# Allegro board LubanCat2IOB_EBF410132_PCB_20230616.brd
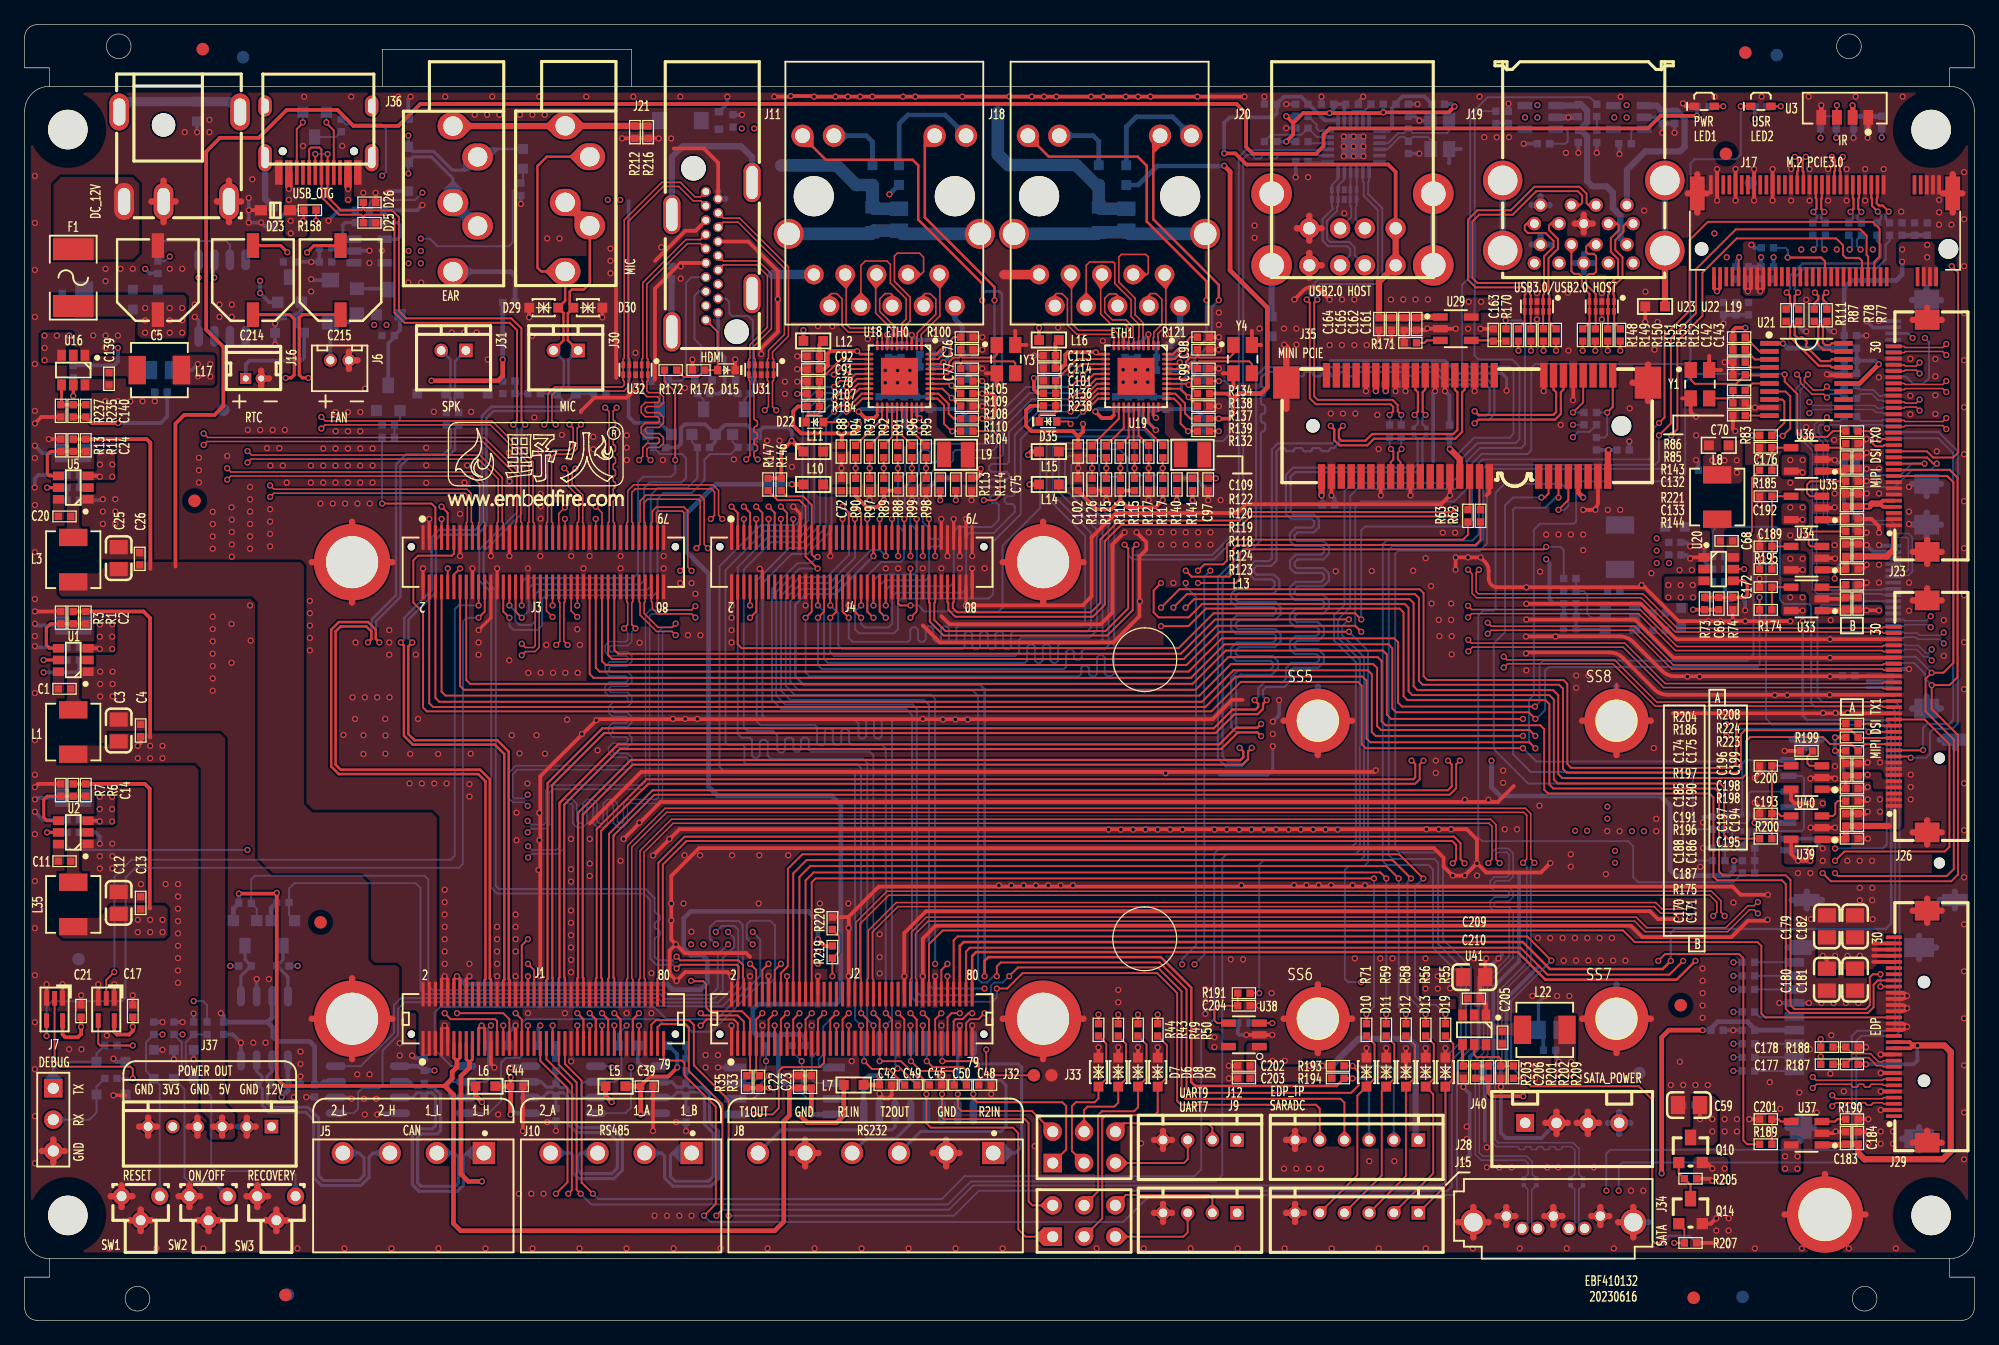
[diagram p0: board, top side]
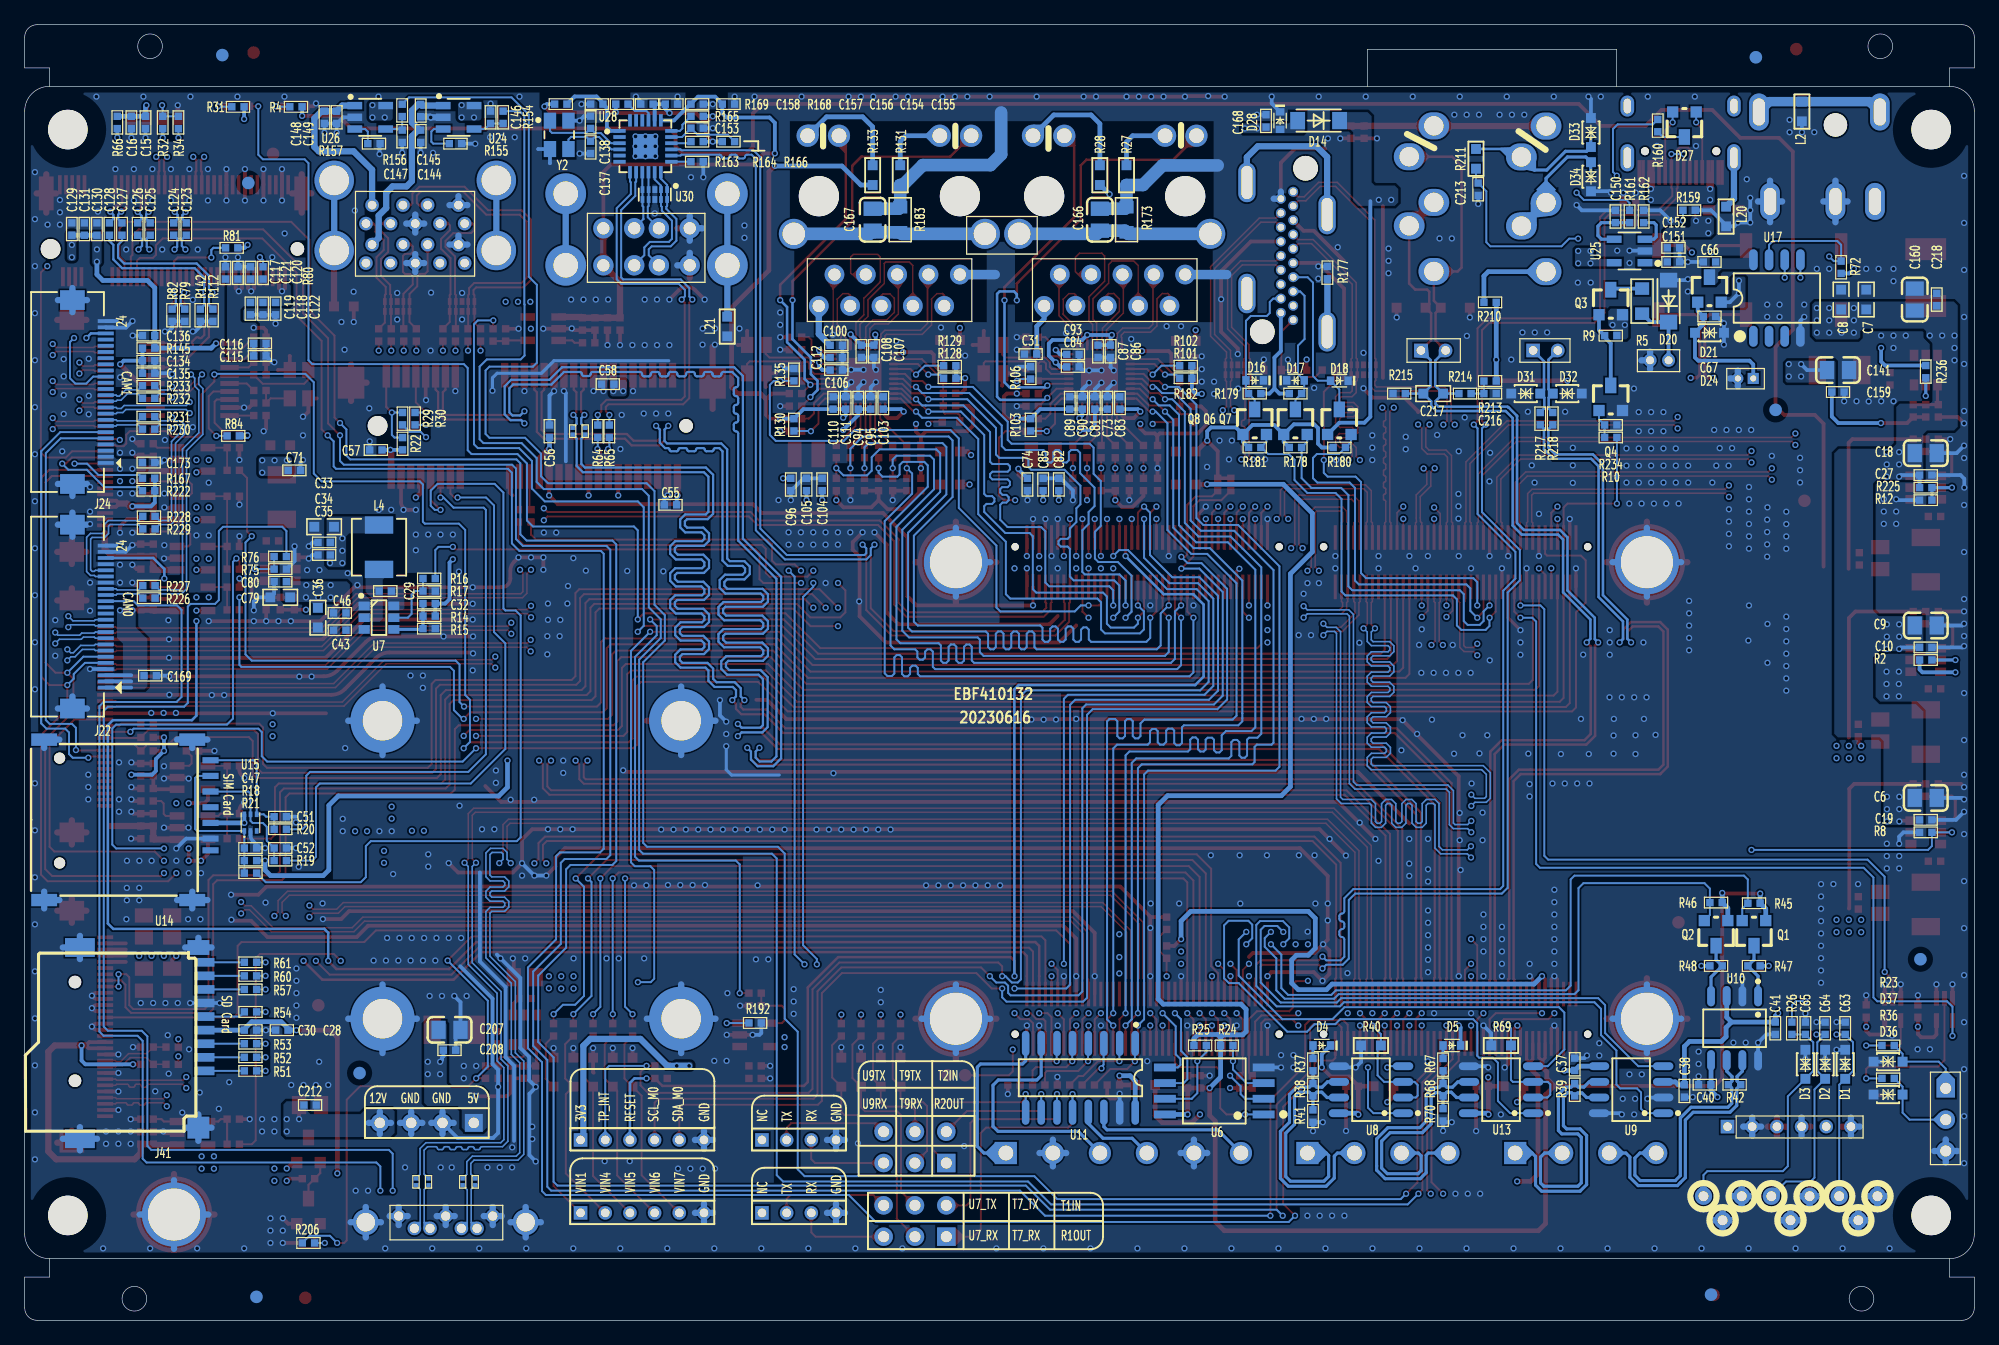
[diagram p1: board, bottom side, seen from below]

Outline 158 x 105 mm; copper layers: TOP, GND02, ART03, ART04, PWR05, BOTTOM. Coordinates in mm from the lower left corner of the outline.
Outline path: circle c7.62,103.25 r1 ; circle c9.14,1.75 r1 ; circle c147.84,103.25 r1 ; circle c149.11,1.75 r1 ; 2,100 arc(0.59,99.41) 0,98 0,7 arc(0.59,5.59) 2,5 ; 2,100 2,101.5 0,101.5 0,104 arc(0.29,104.71) 1,105 157,105 arc(157.71,104.71) 158,104 158,101.5 156,101.5 156,100 ; 2,100 156,100 ; 2,5 2,3.5 0,3.5 0,1 arc(0.29,0.29) 1,0 157,0 arc(157.71,0.29) 158,1 158,3.5 156,3.5 156,5 ; 2,5 156,5 ; 156,5 arc(157.41,5.59) 158,7 158,98 arc(157.41,99.41) 156,100 ; 28.99,100 28.99,103 49.18,103 49.18,100

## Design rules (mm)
net group DIFF_MDI0_PHY0: nets MDIN0_PHY0 MDIP0_PHY0
net group DIFF_MDI0_PHY1: nets MDIN0_PHY1 MDIP0_PHY1
net group DIFF_MDI1_PHY0: nets MDIN1_PHY0 MDIP1_PHY0
net group DIFF_MDI1_PHY1: nets MDIN1_PHY1 MDIP1_PHY1
net group DIFF_MDI2_PHY0: nets MDIN2_PHY0 MDIP2_PHY0
net group DIFF_MDI2_PHY1: nets MDIN2_PHY1 MDIP2_PHY1
net group DIFF_MDI3_PHY0: nets MDIN3_PHY0 MDIP3_PHY0
net group DIFF_MDI3_PHY1: nets MDIN3_PHY1 MDIP3_PHY1
net group DIFF_SATA0RX: nets SATA0RXN SATA0RXP
net group DIFF_SATA0TX: nets SATA0TXN SATA0TXP
net group DIFF_USB2_HOST3_D: nets USB2_HOST3_DM USB2_HOST3_DP
net group DIFF_USB3_HOST1_SSTX: nets USB3_HOST1_SSTXN USB3_HOST1_SSTXP
net group DIFF_USB3_OTG0_D: nets USB3_OTG0_DM USB3_OTG0_DP
net group DIFF_USB30_TX: nets USB30_TXN USB30_TXP
net group DIFF_USB_HUB_D1: nets USB_HUB_DM1 USB_HUB_DP1
net group DIFF_USB_HUB_D2: nets USB_HUB_DM2 USB_HUB_DP2
net group EDP_AUXN: nets EDP_AUXN EDP_TX_AUXN
net group EDP_AUXP: nets EDP_AUXP EDP_TX_AUXP
net group GMAC0_RXCLK: nets GMAC0_RXCLK N15580037
net group GMAC0_RXD0: nets GMAC0_RXD0 N15580021
net group GMAC0_RXD1: nets GMAC0_RXD1 N15580025
net group GMAC0_RXD2: nets GMAC0_RXD2 N15580029
net group GMAC0_RXD3: nets GMAC0_RXD3 N15580033
net group GMAC0_RXDV_CRS: nets GMAC0_RXDV_CRS N15580041
net group GMAC1_RXCLK_M1: nets GMAC1_RXCLK_M1 N15599549
net group GMAC1_RXD0_M1: nets GMAC1_RXD0_M1 N15599533
net group GMAC1_RXD1_M1: nets GMAC1_RXD1_M1 N15599537
net group GMAC1_RXD2_M1: nets GMAC1_RXD2_M1 N15599541
net group GMAC1_RXD3_M1: nets GMAC1_RXD3_M1 N15599545
net group GMAC1_RXDV_CRS_M1: nets GMAC1_RXDV_CRS_M1 N15599553
net group N17639713: nets N17639713 N17697748
net group PCIE20_CLKREQN_M1: nets N17411326 PCIE20_CLKREQN_M1
net group PCIE20_TXN: nets PCIE20_TXN PE_TXN
net group PCIE20_TXP: nets PCIE20_TXP PE_TXP
net group PCIE20_WAKEN_M1: nets N17411312 PCIE20_WAKEN_M1
net group PCIE30_REFCLKN_IN: nets N17639523 PCIE30_REFCLKN_IN
net group PCIE30_REFCLKP_IN: nets N17639486 PCIE30_REFCLKP_IN
net group PCIE30_TX0N: nets PCIE30_TX0N PETN0
net group PCIE30_TX0P: nets PCIE30_TX0P PETP0
net group PCIE30_TX1N: nets PCIE30_TX1N PETN1
net group PCIE30_TX1P: nets PCIE30_TX1P PETP1
net group PWM3_IR: nets N17536407 PWM3_IR
net group SDMMC0_CLK: nets N17407474 SDMMC0_CLK
net group SDMMC0_CMD: nets N17407476 SDMMC0_CMD
net group SDMMC0_D0: nets N17407472 SDMMC0_D0
net group SDMMC0_D1: nets N17407480 SDMMC0_D1
net group SDMMC0_D2: nets N17407470 SDMMC0_D2
net group SDMMC0_D3: nets N17407478 SDMMC0_D3
net group USB20_DM1: nets USB2_HOST2_DM USB20_DM1
net group USB20_DP1: nets USB2_HOST2_DP USB20_DP1
net group USB30_DM: nets USB3_HOST1_DM USB30_DM
net group USB30_DP: nets USB3_HOST1_DP USB30_DP
net group USB30_RXN: nets USB3_HOST1_SSRXN USB30_RXN
net group USB30_RXP: nets USB3_HOST1_SSRXP USB30_RXP
net group USB_HUB_DM3: nets N17411507 USB_HUB_DM3
net group USB_HUB_DP3: nets N17411481 USB_HUB_DP3
net group ADC: nets SARADC_VIN1 SARADC_VIN4 SARADC_VIN5 SARADC_VIN6 SARADC_VIN7
net group FSPI: nets FSPI_CLK FSPI_CS0N FSPI_D0 FSPI_D1 FSPI_D2 FSPI_D3
net group MIPI_CSI_RX_D2N: nets MIPI_CSI_RX_D2N N17546373 N17737043
net group MIPI_CSI_RX_D2P: nets MIPI_CSI_RX_D2P N17546411 N17737040
net group MIPI_CSI_RX_D3N: nets MIPI_CSI_RX_D3N N17546367 N17737138
net group MIPI_CSI_RX_D3P: nets MIPI_CSI_RX_D3P N17546399 N17737126
net group PWR: nets 1V05_AVDD_PHY0 1V05_AVDD_PHY1 1V05_DVDD_PHY0 1V05_DVDD_PHY1 3V3_AVDD_PHY0 3V3_AVDD_PHY1 HUB_3V3 RS232_3V3 RS485_1_3V3 RS485_2_3V3 SIM_VDD VCC3V3_SD VCC5V0_USB20_HOST2 VCC5V0_USB20_HUB VCC5V0_USB30_HOST VCC_1V8 VCCA_1V8 VCCIO_ACODEC VDD_3V3_EDP_LCD VDD_LCD0_3V3
net group REFCLKN: nets N17639617 REF_CLKN REFCLKN
net group REFCLKP: nets N17639615 REF_CLKP REFCLKP

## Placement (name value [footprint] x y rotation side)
C1  0.1uF  [C0402]  3.23 51.18 0 top
C2  NC  [C0402]  4.95 56.94 90 top
C3  22uF  [C0805]  7.62 47.8 90 top
C4  0.1uF  [C0402]  9.4 47.8 90 top
C5  100uF  [EC6P3]  10.79 84.3 180 top
C6  22uF  [C0805]  3.94 42.34 180 bottom
C7  4.7uF  [C0603]  8.76 82.72 90 bottom
C8  0.1uF  [C0603]  10.79 82.72 90 bottom
C9  22uF  [C0805]  3.94 56.31 180 bottom
C10  0.1uF  [C0402]  3.94 54.53 180 bottom
C11  0.1uF  [C0402]  3.23 37.21 0 top
C12  22uF  [C0805]  7.62 33.83 90 top
C13  0.1uF  [C0402]  9.4 33.83 90 top
C14  NC  [C0402]  4.95 42.97 90 top
C15  0.1uF  [C0402]  148.21 97.07 270 bottom
C16  4.7uF  [C0402]  149.35 97.07 270 bottom
C17  0.1uF  [C0402]  8.76 25.07 90 top
C18  22uF  [C0805]  3.94 70.28 180 bottom
C19  0.1uF  [C0402]  3.94 40.56 180 bottom
C20  0.1uF  [C0402]  3.23 65.15 0 top
C21  0.1uF  [C0402]  4.57 25.07 90 top
C22  10uF  [C0402]  62.74 19.33 90 top
C23  0.1uF  [C0402]  63.75 19.33 90 top
C24  NC  [C0402]  4.95 70.91 90 top
C25  22uF  [C0805]  7.62 61.77 90 top
C26  0.1uF  [C0402]  9.32 61.71 90 top
C27  0.1uF  [C0402]  3.94 68.5 180 bottom
C28  10uF  [C0402]  137.16 23.52 0 bottom
C29  0.1uF  [C0402]  128.78 59.1 180 bottom
C30  0.1uF  [C0402]  139.7 23.52 180 bottom
C31  0.1uF  [C0402]  76.48 78.3 0 bottom
C32  NC  [C0402]  125.22 58.09 0 bottom
C33  22uF  [C0603]  133.73 64.31 0 bottom
C34  1uF  [C0402]  133.73 63.04 0 bottom
C35  0.1uF  [C0402]  133.73 62.02 0 bottom
C36  22uF  [C0603]  134.24 56.94 270 bottom
C37  0.1uF  [C0402]  32.38 20.75 90 bottom
C38  0.1uF  [C0402]  23.5 18.59 270 bottom
C39  0.1uF  [C0402]  50.42 18.97 0 top
C40  0.1uF  [C0402]  21.84 19.1 0 bottom
C41  0.1uF  [C0402]  16.13 23.67 270 bottom
C42  0.1uF  [C0402]  69.77 19.07 0 top
C43  10uF  [C0402]  132.46 55.93 0 bottom
C44  0.1uF  [C0402]  39.88 18.97 0 top
C45  0.1uF  [C0402]  73.81 19.07 0 top
C46  0.1uF  [C0402]  132.46 57.32 0 bottom
C47  33pF  [C0402]  139.7 38.27 180 bottom
C48  0.1uF  [C0402]  77.83 19.07 0 top
C49  0.1uF  [C0402]  71.81 19.07 180 top
C50  0.1uF  [C0402]  75.82 19.07 180 top
C51  33pF  [C0402]  137.29 40.81 180 bottom
C52  33pF  [C0402]  137.29 38.27 180 bottom
C53  0.1uF  [C0201]  113.59 72.06 90 bottom
C54  0.1uF  [C0201]  112.57 72.06 90 bottom
C55  0.1uF  [C0402]  105.66 66.09 0 bottom
C56  0.1uF  [C0402]  115.47 72.06 90 bottom
C57  0.1uF  [C0402]  129.54 70.53 0 bottom
C58  0.1uF  [C0402]  110.74 75.87 0 bottom
C59  22uF  [C0805]  134.87 17.45 180 top
C60  10nF  [C0201]  121.49 11.22 270 bottom
C61  10nF  [C0201]  122.5 11.22 270 bottom
C62  10nF  [C0201]  125.27 11.22 270 bottom
C63  0.1uF  [C0402]  10.46 23.67 90 bottom
C64  0.1uF  [C0402]  12.09 23.67 90 bottom
C65  0.1uF  [C0402]  13.69 23.67 90 bottom
C66  0.1uF  [C0402]  21.46 85.77 0 bottom
C67  10uF  [C0402]  21.46 81.35 180 bottom
C68  0.1uF  [C0402]  137.92 63.17 180 top
C69  NC  [C0402]  137.29 58.09 270 top
C70  22uF  [C0603]  137.29 70.91 180 top
C71  0.1uF  [C0402]  136.14 68.88 180 bottom
C72  0.1uF  [C0402]  66.19 67.74 90 top
C73  0.1uF  [C0402]  70.26 74.34 90 bottom
C74  0.1uF  [C0402]  76.73 67.74 270 bottom
C75  4.7uF  [C0402]  76.73 67.74 270 top
C76  18pF  [C0402]  76.35 78.66 0 top
C77  18pF  [C0402]  76.35 77.14 0 top
C78  0.1uF  [C0402]  63.91 76.07 180 top
C79  22uF  [C0603]  137.29 58.59 0 bottom
C80  0.1uF  [C0402]  137.29 59.86 0 bottom
C81  0.1uF  [C0402]  71.27 74.34 90 bottom
C82  0.1uF  [C0402]  74.19 67.74 90 bottom
C83  0.1uF  [C0402]  69.24 74.34 90 bottom
C84  0.1uF  [C0402]  73.05 77.26 180 bottom
C85  0.1uF  [C0402]  75.46 67.74 90 bottom
C86  0.1uF  [C0402]  70 78.53 270 bottom
C87  0.1uF  [C0402]  71.02 78.53 270 bottom
C88  0.1uF  [C0402]  66.19 70.4 270 top
C89  0.1uF  [C0402]  73.3 74.34 90 bottom
C90  0.1uF  [C0402]  72.29 74.34 90 bottom
C91  0.1uF  [C0402]  63.91 77.09 180 top
C92  0.1uF  [C0402]  63.91 78.13 180 top
C93  0.1uF  [C0402]  73.05 78.28 180 bottom
C94  0.1uF  [C0402]  90.45 74.34 90 bottom
C95  0.1uF  [C0402]  89.43 74.34 90 bottom
C96  0.1uF  [C0402]  95.91 67.74 270 bottom
C97  4.7uF  [C0402]  95.91 67.74 270 top
C98  18pF  [C0402]  95.53 78.66 0 top
C99  18pF  [C0402]  95.53 77.14 0 top
C100  0.1uF  [C0402]  92.23 79.02 180 bottom
C101  0.1uF  [C0402]  83.06 76.15 180 top
C102  0.1uF  [C0402]  85.37 67.74 90 top
C103  0.1uF  [C0402]  88.42 74.34 90 bottom
C104  0.1uF  [C0402]  93.37 67.74 90 bottom
C105  0.1uF  [C0402]  94.64 67.74 90 bottom
C106  0.1uF  [C0402]  92.23 77.01 180 bottom
C107  0.1uF  [C0402]  89.18 78.53 270 bottom
C108  0.1uF  [C0402]  90.2 78.53 270 bottom
C109  0.1uF  [C0402]  85.37 70.4 270 top
C110  0.1uF  [C0402]  92.48 74.34 90 bottom
C111  0.1uF  [C0402]  91.47 74.34 90 bottom
C112  0.1uF  [C0402]  92.23 78.02 180 bottom
C113  0.1uF  [C0402]  83.03 78.18 180 top
C114  0.1uF  [C0402]  83.03 77.16 180 top
C115  1uF  [C0402]  138.94 78.15 180 bottom
C116  0.1uF  [C0402]  138.94 79.17 180 bottom
C117  0.1uF  [C0402]  141.73 84.88 90 bottom
C118  0.1uF  [C0402]  138.68 81.99 270 bottom
C119  0.1uF  [C0402]  139.7 81.99 270 bottom
C120  0.1uF  [C0402]  139.7 84.88 90 bottom
C121  0.1uF  [C0402]  140.72 84.88 90 bottom
C122  0.1uF  [C0402]  137.67 81.99 270 bottom
C123  0.22uF  [C0402]  144.91 88.44 90 bottom
C124  0.22uF  [C0402]  145.92 88.44 90 bottom
C125  0.22uF  [C0402]  147.83 88.44 90 bottom
C126  0.22uF  [C0402]  148.84 88.44 90 bottom
C127  0.22uF  [C0402]  150.11 88.44 90 bottom
C128  0.22uF  [C0402]  151.13 88.44 90 bottom
C129  0.1uF  [C0402]  154.18 88.44 90 bottom
C130  0.1uF  [C0402]  152.15 88.44 90 bottom
C131  0.1uF  [C0402]  153.16 88.44 90 bottom
C132  18pF  [C0402]  138.94 76.63 180 top
C133  18pF  [C0402]  138.94 74.34 0 top
C134  0.1uF  [C0402]  147.96 77.77 180 bottom
C135  1uF  [C0402]  147.96 76.75 180 bottom
C136  4.7uF  [C0402]  147.96 79.8 0 bottom
C137  NC  [C0402]  112.14 95.05 270 bottom
C138  NC  [C0402]  112.14 97.09 90 bottom
C139  0.1uF  [C0402]  6.83 76.3 90 top
C140  NC  [C0402]  4.95 73.71 270 top
C141  22uF  [C0805]  11.05 77.01 180 bottom
C142  0.1uF  [C0402]  128.3 79.85 270 top
C143  0.1uF  [C0402]  129.31 79.85 270 top
C144  10uF  [C0402]  125.91 95.96 270 bottom
C145  0.1uF  [C0402]  125.91 98.04 270 bottom
C146  0.1uF  [C0402]  120.24 97.49 90 bottom
C147  0.1uF  [C0402]  127.41 95.96 270 bottom
C148  10uF  [C0402]  133.71 97.49 270 bottom
C149  0.1uF  [C0402]  132.72 97.49 270 bottom
C150  0.1uF  [C0402]  29.08 89.45 90 bottom
C151  10uF  [C0402]  24.38 85.77 180 bottom
C152  0.1uF  [C0402]  24.38 86.91 180 bottom
C153  0.1uF  [C0402]  103.5 96.62 180 bottom
C154  10uF  [C0402]  103.5 98.56 180 bottom
C155  0.1uF  [C0402]  100.97 98.56 180 bottom
C156  0.1uF  [C0402]  105.59 98.56 180 bottom
C157  10uF  [C0402]  107.57 98.56 0 bottom
C158  10nF  [C0402]  111.63 98.56 0 bottom
C159  0.1uF  [C0402]  11.05 75.23 180 bottom
C160  22uF  [C0805]  4.83 82.72 90 bottom
C161  10uF  [C0402]  112.8 80.74 270 top
C162  0.1uF  [C0402]  111.79 80.74 270 top
C163  0.1uF  [C0402]  119.02 79.85 90 top
C164  1uF  [C0402]  109.75 80.74 270 top
C165  1uF  [C0402]  110.77 80.74 270 top
C166  1nF  [C0805]  70.87 89.19 90 bottom
C167  1nF  [C0805]  89.28 89.19 90 bottom
C168  1uF  [C0402]  57.4 97.2 90 bottom
C169  10uF  [C0402]  147.83 52.24 180 bottom
C170  10uF  [C0402]  147.57 58.09 90 top
C171  0.1uF  [C0402]  148.59 58.09 90 top
C172  0.1uF  [C0402]  141.1 59.42 180 top
C173  10uF  [C0402]  147.96 69.52 180 bottom
C174  10uF  [C0402]  147.57 69.52 90 top
C175  0.1uF  [C0402]  148.59 69.52 90 top
C176  0.1uF  [C0402]  141.1 70.72 180 top
C177  0.1uF  [C0402]  146.05 20.75 0 top
C178  0.1uF  [C0402]  146.05 22.14 0 top
C179  10uF  [C0805]  146.05 31.92 90 top
C180  10uF  [C0805]  146.05 27.61 270 top
C181  10uF  [C0805]  148.34 27.61 270 top
C182  10uF  [C0805]  148.34 31.92 90 top
C183  10uF  [C0402]  147.57 14.78 90 top
C184  0.1uF  [C0402]  148.59 14.78 90 top
C185  0.1uF  [C0402]  147.57 66.47 90 top
C186  10uF  [C0402]  148.59 62.4 90 top
C187  10uF  [C0402]  148.08 60.88 0 top
C188  0.1uF  [C0402]  147.57 62.4 90 top
C189  0.1uF  [C0402]  141.1 62.72 180 top
C190  10uF  [C0402]  148.59 66.47 90 top
C191  0.1uF  [C0402]  148.08 64.94 0 top
C192  0.1uF  [C0402]  141.1 66.78 180 top
C193  0.1uF  [C0402]  141.1 41.07 180 top
C194  10uF  [C0402]  148.59 40.56 90 top
C195  0.1uF  [C0402]  148.08 39.04 0 top
C196  0.1uF  [C0402]  147.57 44.62 90 top
C197  10uF  [C0402]  147.57 40.56 90 top
C198  0.1uF  [C0402]  148.08 43.1 0 top
C199  10uF  [C0402]  148.59 44.62 90 top
C200  0.1uF  [C0402]  141.1 44.94 180 top
C201  0.1uF  [C0402]  141.1 16.3 180 top
C202  10uF  [C0402]  98.81 20.62 180 top
C203  0.1uF  [C0402]  98.81 19.6 180 top
C204  0.1uF  [C0402]  98.81 25.5 0 top
C205  0.1uF  [C0402]  119.76 22.91 90 top
C206  NC  [C0402]  117.6 20.11 270 top
C207  22uF  [C0805]  123.57 23.54 180 bottom
C208  0.1uF  [C0402]  123.57 21.89 180 bottom
C209  22uF  [C0805]  117.47 27.81 0 top
C210  0.1uF  [C0402]  117.45 26.08 0 top
C211  10nF  [C0201]  126.29 11.22 270 bottom
C212  0.1uF  [C0402]  134.87 17.45 180 bottom
C213  1uF  [C0402]  40.21 91.66 270 bottom
C214  220uF  [EC6P3]  18.5 84.3 180 top
C215  220uF  [EC6P3]  25.6 84.3 180 top
C216  1uF  [C0402]  39.24 75.1 180 bottom
C217  100pF  [C0603]  43.85 75.1 0 bottom
C218  0.1uF  [C0402]  3.05 82.72 90 bottom
D1  PESD3V3L1BA  [SOD323_T]  10.46 20.75 270 bottom
D2  PESD3V3L1BA  [SOD323_T]  12.09 20.75 270 bottom
D3  PESD3V3L1BA  [SOD323_T]  13.69 20.75 270 bottom
D4  RB521S-30  [SOD523]  52.88 22.27 0 bottom
D5  RB521S-30  [SOD523]  42.34 22.27 0 bottom
D6  PESD3V3L1BA  [SOD323_T]  88.62 20.11 90 top
D7  PESD3V3L1BA  [SOD323_T]  87.02 20.11 90 top
D8  PESD3V3L1BA  [SOD323_T]  90.22 20.11 90 top
D9  PESD3V3L1BA  [SOD323_T]  91.82 20.11 90 top
D10  PESD3V3L1BA  [SOD323_T]  108.74 20.11 90 top
D11  PESD3V3L1BA  [SOD323_T]  110.34 20.11 90 top
D12  PESD3V3L1BA  [SOD323_T]  111.94 20.11 90 top
D13  PESD3V3L1BA  [SOD323_T]  113.54 20.11 90 top
D14  1N5819W  [SOD-123]  53.14 97.23 180 bottom
D15  ESD5B5.0ST1G  [SOD523]  56.87 77.01 180 top
D16  ESD5B5.0ST1G  [SOD523]  58.32 76.17 0 bottom
D17  ESD5B5.0ST1G  [SOD523]  55.02 76.17 180 bottom
D18  ESD5B5.0ST1G  [SOD523]  51.46 76.15 0 bottom
D19  PESD3V3L1BA  [SOD323_T]  115.14 20.11 90 top
D20  1N4148W  [SOD-123]  24.78 82.6 270 bottom
D21  BAT54C  [SOT23]  21.46 83.5 180 bottom
D22  RB521S-30  [SOD523]  64.03 72.79 0 top
D23  PESD5V0S1BA-N  [SOD323]  20.32 89.96 0 top
D24  PESD3V3L1BA  [SOD323_T]  21.46 80.03 0 bottom
D25  KLXES15AAA1  [ES0402]  27.94 88.95 0 top
D26  KLXES15AAA1  [ES0402]  27.94 90.6 0 top
D27  BAT54A  [SOT23]  23.5 96.94 0 bottom
D28  ESD5B5.0ST1G  [SOD523]  56.26 97.23 270 bottom
D29  PESD3V3L1BA  [SOD323_T]  42.06 82.06 180 top
D30  PESD3V3L1BA  [SOD323_T]  45.64 82.06 0 top
D31  PESD3V3L1BA  [SOD323_T]  36.35 75.1 0 bottom
D32  PESD3V3L1BA  [SOD323_T]  32.99 75.1 180 bottom
D33  PESD3V3L1BA  [SOD323_T]  31.07 96.26 90 bottom
D34  PESD3V3L1BA  [SOD323_T]  31.06 92.68 270 bottom
D35  RB521S-30  [SOD523]  82.93 72.84 0 top
D36  PESD3V3L1BA  [SOD323_T]  6.99 18.29 0 bottom
D37  PESD3V3L1BA  [SOD323_T]  6.99 20.96 0 bottom
F1  SMD1812P200TF16  [F1812]  3.94 84.5 270 top
J1  -  [SGDBM-05-80P-H10]  42.03 24.44 0 top
J2  -  [SGDBM-05-80P-H10]  67.03 24.44 0 top
J3  -  [SGDBF-05-80P-H30]  42.03 61.44 180 top
J4  -  [SGDBF-05-80P-H30]  67.03 61.44 180 top
J5  CON4  [DB2ERC-3P81-4P]  31.5 13.56 180 top
J6  A1501WV-2P  [ZH1P5MM_TH_2P]  25.53 77.8 0 top
J7  1X3PIN-M  [DIP_3P_2P54]  2.32 16.26 270 top
J8  CON6  [DB2ERC-3P81-6P]  68.96 13.56 180 top
J9  PH-4A  [PH-1X4-2P0]  95.25 8.71 180 top
J10  CON4  [DB2ERC-3P81-4P]  48.33 13.56 180 top
J11  -  [HY911130A]  69.66 91.1 0 top
J12  PH-4A  [PH-1X4-2P0]  95.25 14.62 180 top
J13  2X3PIN-M  [DIP-2X3-2P54]  85.85 8.05 0 top
J14  2X3PIN-M  [DIP-2X3-2P54]  85.85 14.02 0 top
J15  PH-6A  [PH-1X6-2P0]  107.95 8.71 180 top
J16  1.25T-2A  [GH1P25_TH_2P]  18.54 76.33 0 top
J17  -  [M2_NGFF_M_KEY]  145.9 88.3 0 top
J18  -  [HY911130A]  87.92 91.1 0 top
J19  USB3D0_USB2D0-A-D  [USB3D0-AF-18P]  126.35 88.88 180 top
J20  -  [USB-A-D]  107.6 92 0 top
J21  HDMI-001C  [HDMI-SMD]  55.7 86.16 90 top
J22  FPC_0P5_24P_D  [FPC_24P_0P5]  152.78 57.03 90 bottom
J23  FPC_0R5_30P_D  [FPC-30P-0P5]  152.83 71.67 90 top
J24  FPC_0P5_24P_D  [FPC_24P_0P5]  152.78 75.23 90 bottom
J25  PJ-325C5-G  [EAR_JACK]  34.71 90.58 270 top
J26  FPC_0R5_30P_D  [FPC-30P-0P5]  152.83 48.94 90 top
J27  PJ-325C5-R  [EAR_JACK]  43.8 90.6 270 top
J28  PH-6A  [PH-1X6-2P0]  107.95 14.62 180 top
J29  FPC_0R5_30P_D  [FPC-30P-0P5]  152.83 23.8 90 top
J30  PH  [PH-1X2-2P0_L]  43.85 78.6 180 top
J31  PH  [PH-1X2-2P0_L]  34.76 78.6 180 top
J32  TP  [TP_1MM]  81.79 19.86 180 top
J33  TP  [TP_1MM]  83.21 19.86 180 top
J34  SATA  [SSATA_V]  123.88 8.45 0 top
J35  MINI-PCIE  [PCIE_52P]  116.9 72.49 180 top
J36  TYPE-C  [TYPE-C-31-M-12]  23.8 93.31 180 top
J37  PH-6A  [PH-1X6-2P0]  15 15.7 180 top
J39  DC-044A-20A  [DC_IN_TH_3P_10R1X11R6]  12.55 94.3 270 top
J40  CON4  [XH2P54-4P]  125.41 16 0 top
J41  TF_Card  [TFCARD]  153.92 23.41 270 bottom
L1  3.3uH  [L4520]  3.93 47.67 270 top
L2  100R 100MHz  [L0603]  13.97 97.96 270 bottom
L3  3.3uH  [L4520]  3.93 61.64 270 top
L4  3.3uH  [L4520]  129.28 62.66 90 bottom
L5  100R 100MHz  [L0603]  47.88 18.97 0 top
L6  100R 100MHz  [L0603]  37.34 18.97 0 top
L7  100R 100MHz  [L0603]  67.18 19.07 180 top
L8  3.3uH  [L4520]  137.16 66.72 90 top
L9  2.2uH  [L2520]  75.46 70.15 0 top
L10  100R 100MHz  [L0603]  63.91 67.74 180 top
L11  100R 100MHz  [L0603]  63.91 70.4 180 top
L12  100R 100MHz  [L0603]  63.91 79.37 180 top
L13  2.2uH  [L2520]  94.64 70.15 0 top
L14  100R 100MHz  [L0603]  83.01 67.74 180 top
L15  100R 100MHz  [L0603]  83.01 70.4 180 top
L16  100R 100MHz  [L0603]  83.01 79.45 180 top
L17  3.3uH  [L4520]  10.92 77.01 0 top
L19  100R 100MHz  [L0603]  132.13 82.17 180 top
L20  100R 100MHz  [L0603]  20.12 89.45 270 bottom
L21  100R 100MHz  [L0603]  101.07 80.54 270 bottom
L22  3.3uH  [L4520]  123.19 23.54 0 top
L35  3.3uH  [L4520]  3.93 33.7 270 top
LED1  HS-0602-UR  [LED_HS_0602_UR]  136.1 98.39 0 top
LED2  HS-0602-UG  [LED_HS_0602_UR]  140.7 98.39 0 top
NOREF  -  [unnamed]  13.77 66.42 0 top
NOREF#2  -  [unnamed]  21.13 2.05 0 top
NOREF#3  -  [unnamed]  137.87 94.53 0 top
NOREF#4  -  [#2]  0 7.1 0 top
NOREF#5  -  [unnamed]  139.45 102.74 0 top
NOREF#6  -  [unnamed]  134.2 25.53 0 top
NOREF#7  -  [unnamed]  23.98 32.25 0 top
NOREF#8  -  [unnamed]  135.25 1.82 0 top
NOREF#9  -  [#2]  2 5 90 top
NOREF#10  -  [unnamed]  14.43 103.02 0 top
NOREF#11  -  [unnamed]  139.88 92.17 180 bottom
NOREF#12  -  [unnamed]  16.1 73.78 180 bottom
NOREF#13  -  [unnamed]  141.99 102.54 180 bottom
NOREF#14  -  [unnamed]  139.22 1.9 180 bottom
NOREF#15  -  [unnamed]  17.7 102.36 180 bottom
NOREF#16  -  [unnamed]  21.34 2.08 180 bottom
NOREF#17  -  [unnamed]  4.37 29.26 180 bottom
NOREF#18  -  [unnamed]  130.86 20.04 180 bottom
Q1  2SK3018  [SOT23]  17.86 31.4 0 bottom
Q2  2SK3018  [SOT23]  20.93 31.4 0 bottom
Q3  SSM3J328R-LF  [SOT23]  29.46 82.48 180 bottom
Q4  SS8050  [SOT23]  29.46 74.72 180 bottom
Q6  2SK3018  [SOT23]  55.02 72.78 180 bottom
Q7  2SK3018  [SOT23]  51.46 72.78 180 bottom
Q8  2SK3018  [SOT23]  58.32 72.78 180 bottom
Q10  SSM3J328R-LF  [SOT23]  135 13.78 0 top
Q14  2SK3018  [SOT23]  135 8.82 0 top
R1  115K  [R0402]  3.94 56.94 90 top
R2  1K  [R0402]  3.94 53.51 0 bottom
R3  20K  [R0402]  2.92 56.94 90 top
R4  5.1K  [R0402]  136.02 98.34 0 bottom
R5  10R  [R0805]  26.92 82.6 270 bottom
R6  100K  [R0402]  3.94 42.97 90 top
R7  30K  [R0402]  2.92 42.97 90 top
R8  1K  [R0402]  3.94 39.54 0 bottom
R9  10K  [R0402]  29.46 79.8 0 bottom
R10  1K  [R0402]  29.46 71.55 0 bottom
R11  115K  [R0402]  3.94 70.91 90 top
R12  27K  [R0402]  3.94 66.47 0 bottom
R13  20K  [R0402]  2.92 70.91 90 top
R14  100K  [R0402]  125.22 57.07 0 bottom
R15  30K  [R0402]  125.22 56.05 180 bottom
R16  1K  [R0402]  125.22 60.12 0 bottom
R17  10K  [R0402]  125.22 59.1 180 bottom
R18  15K  [R0402]  139.7 37.26 0 bottom
R19  0R  [R0402]  137.29 37.26 0 bottom
R20  0R  [R0402]  137.29 39.8 0 bottom
R21  0R  [R0402]  139.7 36.24 0 bottom
R22  4.7K  [R0402]  127.38 71.04 90 bottom
R23  100R  [R0402]  6.99 22.27 0 bottom
R24  10K  [R0402]  60.58 22.27 180 bottom
R25  10K  [R0402]  62.74 22.27 180 bottom
R26  100R  [R0402]  14.78 23.67 90 bottom
R27  510R  [R0603]  68.71 92.81 270 bottom
R28  510R  [R0603]  70.87 92.81 270 bottom
R29  22R  [R0402]  127.38 73.07 90 bottom
R30  22R  [R0402]  126.36 73.07 90 bottom
R31  4.7K  [R0402]  140.72 98.34 0 bottom
R32  10K  [R0402]  146.81 97.07 90 bottom
R33  2.2K  [R0402]  59.54 19.33 90 top
R34  22R  [R0402]  145.54 97.07 90 bottom
R35  2.2K  [R0402]  58.52 19.33 90 top
R36  100R  [R0402]  6.99 19.6 0 bottom
R37  4.7K  [R0402]  53.59 20.72 90 bottom
R38  120R  [R0402]  53.59 18.69 90 bottom
R39  120R  [R0402]  32.38 18.69 90 bottom
R40  10K  [R0603]  48.9 22.27 0 bottom
R41  4.7K  [R0402]  53.59 16.56 270 bottom
R42  120R  [R0402]  19.43 19.1 0 bottom
R43  100R  [R0402]  88.62 23.54 270 top
R44  100R  [R0402]  87.02 23.54 270 top
R45  10K  [R0402]  17.86 33.8 0 bottom
R46  10K  [R0402]  20.93 33.85 0 bottom
R47  10K  [R0402]  17.86 28.72 0 bottom
R48  10K  [R0402]  20.93 28.72 180 bottom
R49  100R  [R0402]  90.22 23.54 270 top
R50  100R  [R0402]  91.82 23.54 270 top
R51  22R  [R0402]  139.7 20.22 0 bottom
R52  22R  [R0402]  139.7 21.32 0 bottom
R53  22R  [R0402]  139.7 22.41 0 bottom
R54  22R  [R0402]  139.7 25 0 bottom
R55  100R  [R0402]  115.14 23.54 270 top
R56  100R  [R0402]  113.54 23.54 270 top
R57  22R  [R0402]  139.7 26.81 0 bottom
R58  100R  [R0402]  111.94 23.54 270 top
R59  100R  [R0402]  110.34 23.54 270 top
R60  22R  [R0402]  139.7 27.92 0 bottom
R61  0R  [R0402]  139.7 29.02 0 bottom
R62  1K  [R0402]  117.98 65.2 270 top
R63  1K  [R0402]  116.97 65.2 270 top
R64  2.2R  [R0402]  111.56 72.06 90 bottom
R65  2.2R  [R0402]  110.62 72.06 90 bottom
R66  22R  [R0402]  150.5 97.07 270 bottom
R67  4.7K  [R0402]  43.05 20.72 90 bottom
R68  120R  [R0402]  43.05 18.69 90 bottom
R69  10K  [R0603]  38.35 22.27 0 bottom
R70  4.7K  [R0402]  43.05 16.66 270 bottom
R71  100R  [R0402]  108.74 23.54 270 top
R72  4.7K  [R0402]  10.79 85.34 90 bottom
R73  100K  [R0402]  136.14 58.09 270 top
R74  30K  [R0402]  138.43 58.09 270 top
R75  10K  [R0402]  137.29 60.88 180 bottom
R76  1K  [R0402]  137.29 61.9 180 bottom
R77  33R  [R0402]  146.05 81.45 90 top
R78  33R  [R0402]  145.03 81.45 90 top
R79  49.9R  [R0402]  145.03 81.45 270 bottom
R80  10K  [R0402]  138.68 84.88 270 bottom
R81  10K  [R0402]  141.22 86.91 180 bottom
R82  49.9R  [R0402]  146.05 81.45 270 bottom
R83  10K  [R0402]  141.1 71.73 0 top
R84  4.7K  [R0402]  141.1 71.67 0 bottom
R85  10K  [R0402]  138.94 78.66 0 top
R86  10K  [R0402]  138.94 79.68 0 top
R87  33R  [R0402]  143.76 81.45 90 top
R88  4.7K  [R0402]  70.76 67.74 90 top
R89  4.7K  [R0402]  69.62 67.74 90 top
R90  4.7K  [R0402]  67.34 67.74 90 top
R91  22R  [R0402]  70.76 70.4 90 top
R92  22R  [R0402]  69.62 70.4 90 top
R93  22R  [R0402]  68.48 70.4 90 top
R94  22R  [R0402]  67.34 70.4 90 top
R95  22R  [R0402]  73.05 70.4 90 top
R96  22R  [R0402]  71.91 70.4 90 top
R97  4.7K  [R0402]  68.48 67.74 270 top
R98  4.7K  [R0402]  73.05 67.74 270 top
R99  4.7K  [R0402]  71.91 67.74 270 top
R100  2.49K  [R0402]  76.35 79.68 0 top
R101  4.7K  [R0402]  63.91 76.35 0 bottom
R102  4.7K  [R0402]  63.91 77.36 0 bottom
R103  4.7K  [R0402]  76.48 72.57 270 bottom
R104  NC  [R0402]  76.35 72.06 180 top
R105  100R  [R0402]  76.35 76.12 180 top
R106  120R  [R0402]  76.48 76.78 90 bottom
R107  10K  [R0402]  63.91 75.08 0 top
R108  4.7K  [R0402]  76.35 74.09 0 top
R109  4.7K  [R0402]  76.35 75.1 0 top
R110  4.7K  [R0402]  76.35 73.07 0 top
R111  33R  [R0402]  142.75 81.45 90 top
R112  49.9R  [R0402]  142.75 81.45 270 bottom
R113  0R  [R0402]  74.19 67.74 90 top
R114  0R  [R0402]  75.46 67.74 270 top
R115  4.7K  [R0402]  89.94 67.74 90 top
R116  4.7K  [R0402]  88.8 67.74 90 top
R117  4.7K  [R0402]  92.23 67.74 90 top
R118  22R  [R0402]  89.94 70.4 90 top
R119  22R  [R0402]  88.8 70.4 90 top
R120  22R  [R0402]  87.66 70.4 90 top
R121  2.49K  [R0402]  95.53 79.68 0 top
R122  22R  [R0402]  86.51 70.4 90 top
R123  22R  [R0402]  92.23 70.4 90 top
R124  22R  [R0402]  91.08 70.4 90 top
R125  4.7K  [R0402]  87.66 67.74 270 top
R126  4.7K  [R0402]  86.51 67.74 270 top
R127  4.7K  [R0402]  91.08 67.74 270 top
R128  4.7K  [R0402]  83.03 76.35 0 bottom
R129  4.7K  [R0402]  83.03 77.36 0 bottom
R130  4.7K  [R0402]  95.66 72.57 270 bottom
R131  510R  [R0603]  87.05 92.81 270 bottom
R132  NC  [R0402]  95.53 72.06 180 top
R133  510R  [R0603]  89.28 92.81 270 bottom
R134  100R  [R0402]  95.53 76.12 180 top
R135  120R  [R0402]  95.66 76.64 90 bottom
R136  10K  [R0402]  83.06 75.13 0 top
R137  4.7K  [R0402]  95.53 74.09 0 top
R138  4.7K  [R0402]  95.53 75.1 0 top
R139  4.7K  [R0402]  95.53 73.07 0 top
R140  0R  [R0402]  93.37 67.74 90 top
R141  0R  [R0402]  94.64 67.74 270 top
R142  49.9R  [R0402]  143.76 81.45 270 bottom
R143  10K  [R0402]  138.94 77.64 180 top
R144  470R  [R0402]  138.94 73.33 180 top
R145  2.2R  [R0402]  147.96 78.79 180 bottom
R146  2.2K  [R0402]  61.32 67.74 270 top
R147  2.2K  [R0402]  60.25 67.74 270 top
R148  2.2R  [R0402]  121.06 79.85 270 top
R149  2.2R  [R0402]  122.07 79.85 270 top
R150  2.2R  [R0402]  123.09 79.85 270 top
R151  2.2R  [R0402]  124.1 79.85 270 top
R152  2.2R  [R0402]  127.28 79.85 270 top
R153  2.2R  [R0402]  126.26 79.85 270 top
R154  1K  [R0402]  119.23 97.49 270 bottom
R155  3.4K  [R0402]  123.09 95.36 180 bottom
R156  1K  [R0402]  127.41 98.05 270 bottom
R157  3.4K  [R0402]  129.69 95.36 180 bottom
R158  10K  [R0402]  23.11 89.96 0 top
R159  15K  [R0402]  23.11 89.96 180 bottom
R160  100R  [R0402]  25.65 96.82 90 bottom
R161  1K  [R0402]  27.94 89.45 270 bottom
R162  3.4K  [R0402]  26.8 89.45 90 bottom
R163  2.7K  [R0402]  103.5 93.9 180 bottom
R164  100K  [R0402]  103.5 95.52 180 bottom
R165  100K  [R0402]  103.5 97.58 180 bottom
R166  10K  [R0402]  100.97 95.52 0 bottom
R167  NC  [R0402]  147.96 68.25 0 bottom
R168  1K  [R0402]  109.6 98.56 0 bottom
R169  10K  [R0402]  114.55 98.56 180 bottom
R170  1K  [R0402]  120.04 79.85 270 top
R171  3.4K  [R0402]  112.29 79.22 180 top
R172  1K  [R0402]  52.35 77.01 0 top
R173  1M  [R0805]  68.71 89.19 90 bottom
R174  1K  [R0402]  141.1 57.58 0 top
R175  3.4K  [R0402]  148.08 59.61 0 top
R176  100K  [R0402]  54.61 77.01 180 top
R177  0R  [R0402]  52.43 84.91 90 bottom
R178  10K  [R0402]  55.02 70.74 180 bottom
R179  4.7K  [R0402]  55.02 75.1 180 bottom
R180  27K  [R0402]  51.46 70.74 180 bottom
R181  10K  [R0402]  58.32 70.74 180 bottom
R182  4.7K  [R0402]  58.32 75.1 0 bottom
R183  1M  [R0805]  87.05 89.19 90 bottom
R184  NC  [R0402]  63.91 74.06 0 top
R185  1K  [R0402]  141.1 68.88 0 top
R186  3.4K  [R0402]  148.08 71.04 0 top
R187  NC  [R0402]  148.08 20.75 180 top
R188  NC  [R0402]  148.08 22.14 180 top
R189  1K  [R0402]  141.1 14.27 180 top
R190  3.4K  [R0402]  148.08 16.3 0 top
R191  1K  [R0402]  98.81 26.51 180 top
R192  3.4K  [R0402]  98.81 24.1 180 bottom
R193  10K  [R0402]  106.43 20.62 0 top
R194  10K  [R0402]  106.43 19.6 0 top
R195  1K  [R0402]  141.1 60.88 0 top
R196  3.4K  [R0402]  148.08 63.93 0 top
R197  3.4K  [R0402]  148.08 67.99 0 top
R198  3.4K  [R0402]  148.08 42.08 0 top
R199  3.4K  [R0402]  144.4 46.15 180 top
R200  1K  [R0402]  141.1 39.04 180 top
R201  115K  [R0402]  118.62 20.11 270 top
R202  10K  [R0402]  119.63 20.11 270 top
R203  20K  [R0402]  116.59 20.11 270 top
R204  0R  [R0402]  148.08 72.06 0 top
R205  10K  [R0402]  135 11.48 180 top
R206  1K  [R0402]  135 6.27 180 bottom
R207  10K  [R0402]  135 6.27 0 top
R208  0R  [R0402]  148.08 48.36 0 top
R209  1K  [R0402]  120.65 20.11 270 top
R210  10K  [R0402]  39.24 82.5 0 bottom
R211  20R  [R0603]  40.39 94.13 90 bottom
R212  0R  [R0402]  49.45 96.29 270 top
R213  120R  [R0402]  39.24 76.12 0 bottom
R214  2.2K  [R0402]  41.27 75.1 0 bottom
R215  2.2K  [R0402]  46.61 75.1 0 bottom
R216  0R  [R0402]  50.52 96.29 270 top
R217  0R  [R0402]  35.18 73.07 90 bottom
R218  0R  [R0402]  34.16 73.07 90 bottom
R219  25.5K  [R0402]  65.46 29.84 270 top
R220  10K  [R0402]  65.46 32.18 90 top
R221  22R  [R0402]  138.94 75.36 0 top
R222  NC  [R0402]  147.96 67.23 0 bottom
R223  NC  [R0402]  148.08 46.15 0 top
R224  NC  [R0402]  148.08 47.24 0 top
R225  180K  [R0402]  3.94 67.48 0 bottom
R226  NC  [R0402]  147.93 58.52 0 bottom
R227  NC  [R0402]  147.93 59.54 0 bottom
R228  NC  [R0402]  147.93 65.15 0 bottom
R229  NC  [R0402]  147.93 64.14 0 bottom
R230  0R  [R0402]  147.96 72.22 0 bottom
R231  0R  [R0402]  147.96 73.24 0 bottom
R232  0R  [R0402]  147.96 74.72 0 bottom
R233  0R  [R0402]  147.96 75.74 0 bottom
R234  10K  [R0402]  29.46 72.56 180 bottom
R235  115K  [R0402]  3.94 73.71 270 top
R236  1K  [R0402]  3.94 76.88 90 bottom
R237  20K  [R0402]  2.92 73.71 270 top
R238  NC  [R0402]  83.06 74.11 0 top
SS1  -  [NPTH_M3]  3.5 8.5 0 top
SS2  -  [NPTH_M3]  154.5 96.5 0 top
SS3  -  [NPTH_M3]  154.5 8.5 0 top
SS4  -  [NPTH_M3]  3.5 96.5 0 top
SS5  M2X3mm  [T3R2-5R2_TOPSMT]  104.8 48.59 0 top
SS6  M2X3mm  [T3R2-5R2_TOPSMT]  104.8 24.44 0 top
SS7  M2X3mm  [T3R2-5R2_TOPSMT]  129 24.44 0 top
SS8  M2X3mm  [T3R2-5R2_TOPSMT]  129 48.59 0 top
SS9  M3X3.5mm  [SMTSO-M3]  145.9 8.57 0 top
SS10  M2.5X4mm  [SMTSO-M2R5]  82.53 24.44 0 top
SS11  M2.5X4mm  [SMTSO-M2R5]  26.53 24.44 0 top
SS12  M2.5X4mm  [SMTSO-M2R5]  26.53 61.44 0 top
SS13  M2.5X4mm  [SMTSO-M2R5]  82.53 61.44 0 top
SW1  TS-1091B-A5B3-D2  [SW_TH_3P_4R5X5R5]  9.4 9.08 0 top
SW2  TS-1091B-A5B3-D2  [SW_TH_3P_4R5X5R5]  14.9 9.08 0 top
SW3  TS-1091B-A5B3-D2  [SW_TH_3P_4R5X5R5]  20.4 9.08 0 top
U1  TP6327GS6  [SOT23_6]  3.94 53.51 90 top
U2  TP6327GS6  [SOT23_6]  3.94 39.54 90 top
U3  IRM-V838M3-C/TR1  [SMD4-6R80X2R50]  147.5 97.49 0 top
U4  74LVC1G125GW  [SOT-353]  6.61 25.19 180 top
U5  TP6327GS6  [SOT23_6]  3.94 67.48 90 top
U6  W25Q32JWSSIQ/NC  [SOIC8-208]  61.59 18.59 0 bottom
U7  TP6327GS6  [SOT23_6]  129.29 56.94 270 bottom
U8  MAX3485  [SOP8]  48.9 18.69 0 bottom
U9  TJA1042T  [SOP8]  27.81 18.69 0 bottom
U10  TJA1042T  [SOP8]  19.43 23.67 270 bottom
U11  MAX3232CSE  [SOIC16]  72.44 19.66 270 bottom
U12  74LVC1G125GW  [SOT-353]  2.42 25.19 180 top
U13  MAX3485  [SOP8]  38.35 18.69 0 bottom
U14  SIM-7-1  [NANO_SIM]  149.68 40.56 270 bottom
U15  NUP5120X6T1G  [SOT563]  139.7 40.33 180 bottom
U16  TP6327GS6  [SOT23_6]  3.94 77.01 180 top
U17  RX8010SJ  [SOP-8]  16 82.85 180 bottom
U18  JL2101-N040C  [QFP_40P_R]  70.89 76.5 270 top
U19  JL2101-N040C  [QFP_40P_R]  90.07 76.5 270 top
U20  TP6327GS6  [SOT23_6]  137.29 60.88 270 top
U21  PI6C557-05BLE  [TSSOP20]  144.4 76.25 270 top
U22  RCLAMP0524P  [USON_10]  127.81 82.17 180 top
U23  RCLAMP0524P  [USON_10]  122.56 82.17 180 top
U24  MT9700  [SOT23-5]  122.83 97.49 270 bottom
U25  MT9700  [SOT23-5]  27.94 86.66 90 bottom
U26  MT9700  [SOT23-5]  130 97.49 270 bottom
U28  FE1.1s-BQFN24B  [QFN24]  107.7 95.14 180 bottom
U29  MT9700  [SOT23-5]  115.98 80.36 270 top
U30  RCLAMP0524P  [USON_10]  106.93 91.23 0 bottom
U31  RCLAMP0524P  [USON_10]  59.69 77.03 180 top
U32  RCLAMP0524P  [USON_10]  49.5 77.03 180 top
U33  MT9700  [SOT23-5]  144.4 58.47 90 top
U34  MT9700  [SOT23-5]  144.4 61.77 90 top
U35  MT9700  [SOT23-5]  144.4 65.83 90 top
U36  MT9700  [SOT23-5]  144.4 69.77 90 top
U37  MT9700  [SOT23-5]  144.4 15.16 90 top
U38  MT9700  [SOT23-5]  98.81 23.14 90 top
U39  MT9700  [SOT23-5]  144.4 39.92 90 top
U40  MT9700  [SOT23-5]  144.4 43.99 90 top
U41  TP6327GS6  [SOT23_6]  117.47 23.54 180 top
Y1  25MHz  [3225]  135.76 75.87 270 top
Y2  12MHz  [3225]  114.68 96.07 270 bottom
Y3  25MHz  [3225]  79.53 77.9 270 top
Y4  25MHz  [3225]  98.7 77.9 270 top

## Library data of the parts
C1-C4 C6-C52 C55-C122 C129-C176 C179-C213 C216-C218 = CAP_NP
C5 C214 C215 = CAP
C53 C54 C177 C178 = CAP_NP: signal model: CAP_NP_C0402_DISCRETE_0.1UF_0.1uF
C123-C128 = CAP_NP: signal model: CAP_NP_C0402_DISCRETE_0.22UF_0.22uF
D1-D3 D6-D13 D15-D19 D23-D26 D28-D34 D36 D37 = DIODE BI-DIR TRIG
D4 D5 D14 D22 D35 = DIODE_SCHTKY
D20 = DIODE
D21 = BAT54C
D27 = BAT54A
F1 = FUSE
J1-J4 = SGDBM-05-80P-H10
J5 J10 J40 = CON4
J6 = A1501WV-2P
J7 = 1X3PIN
J8 = CON6
J9 J12 = 1X4PIN
J11 J18 = HY911130A
J13 J14 = 2X3PIN
J15 J28 J37 = 1X6PIN
J16 = 1.25T-2A
J17 = M2_NGFF_M_KEY
J19 = USB3D0_USB2D0-A-D
J20 = USB-A-D
J21 = HDMI-001C
J22 J24 = FPC-24P
J23 J26 J29 = FPC-30P
J25 J27 = MIC_JACK
J30 J31 = 1X2PIN
J32 J33 = TEST
J34 = SATA
J35 = MINI-PCIE
J36 = TYPE-C-31-M-12
J39 = DC-044A-20A
J41 = TF_Card
L1 L3 L4 L8 L9 L13 L17 L22 L35 = IND
L2 L5-L7 L10-L12 L14-L16 L19-L21 = BEAD
LED1 LED2 = LED
Q1 Q2 Q6-Q8 Q14 = 2SK3018
Q3 Q10 = MOSFET_P
Q4 = NPN
R1-R28 R31-R33 R35-R50 R55 R56 R58 R59 R61-R63 R67-R76 R79-R86 R88-R90 R97-R110 R112-R117 R121 R125-R144 R146 R147 R154-R220 R222-R225 R234-R238 = RES
R29 R30 R34 R51-R54 R57 R60 R66 R91-R96 R118-R120 R122-R124 R221 = RES: signal model: RES_R0402_DISCRETE_22R_22R
R64 R65 R145 R148-R153 = RES: signal model: RES_R0402_DISCRETE_2.2R_2.2R
R77 R78 R87 R111 = RES: signal model: RES_R0402_DISCRETE_33R_33R
R226-R229 = RES: signal model: RES_R0402_DISCRETE_NC_NC
R230-R233 = RES: signal model: RES_R0402_DISCRETE_0R_0R
SS1-SS13 = SPACER
SW1-SW3 = SW_TH3P
U1 U2 U5 U7 U16 U20 U41 = TP6327GS6
U3 = IRM-V838M3-C/TR1
U4 U12 = 74LVC1G125
U6 = W25QXX_8P
U8 U13 = TJA1057GT3
U9 U10 = TJA1057GT3_8P
U11 = MAX3232CSE
U14 = SIM-7-1
U15 = NUP5120-D
U17 = RX8010SJ
U18 U19 = RTL8211F
U21 = PI6C557-05BLE
U22 U23 U30 U31 = RCLAMP0524P
U24-U26 U29 U33-U40 = MT9700
U28 = FE1.1s-BQFN24B
U32 = RCLAMP0524P: signal model: RCLAMP0524P_USON_10_RCLAMP0524P_RCLAMP0524P
Y1-Y4 = CRYSTAL_4P

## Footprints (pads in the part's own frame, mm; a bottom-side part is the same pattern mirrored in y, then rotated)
3225
  rect 1.3x1 smd: 1(-1.15,-0.75) 2(1.15,-0.75) 3(1.15,0.75) 4(-1.15,0.75)
C0201
  rect 0.35x0.35 smd: 1(-0.275,0) 2(0.275,0)
C0402
  rect 0.599x0.599 smd: 1(-0.5,0) 2(0.5,0)
C0603
  rect 0.8x0.8 smd: 1(-0.8,0) 2(0.8,0)
C0805
  rect 1.16x1.47 smd: 1(-0.89,0) 2(0.89,0)
DB2ERC-3P81-4P
  rect 1.8x1.8 hole 1.2: 1(-5.715,0)
  round 1.8 hole 1.2: 2(-1.905,0) 3(1.905,0) 4(5.715,0)
DB2ERC-3P81-6P
  rect 1.8x1.8 hole 1.2: 1(-9.525,0)
  round 1.8 hole 1.2: 2(-5.715,0) 3(-1.905,0) 4(1.905,0) 5(5.715,0) 6(9.525,0)
DC_IN_TH_3P_10R1X11R6
  round 1.9 hole 1.9 unplated: (-2.575,-1.3)
  oval 3x1.6 hole 2.2x1: 1(-3.625,-4.9) 2(3.625,-1.3) 3(3.625,4) 4(3.625,-4.5) 5(-3.625,4.9)
DIP-2X3-2P54
  rect 1.5x1.5 hole 0.9: 1(-2.54,-1.27)
  round 1.5 hole 0.9: 2(-2.54,1.27) 3(0,-1.27) 4(0,1.27) 5(2.54,-1.27) 6(2.54,1.27)
DIP_3P_2P54
  rect 1.5x1.5 hole 0.9: 1(-2.54,0)
  round 1.5 hole 0.9: 2(0,0) 3(2.54,0)
EAR_JACK
  oval 2.184x2.489 hole 1.575: 1(5.6,0) 2(-3.7,2) 3(1.9,2) 4(0,0) 5(-6.2,0)
EC6P3
  rect 1.001x1.999 smd: 1(0,2.8) 2(0,-2.8)
ES0402
  rect 0.599x0.599 smd: 1(-0.5,0) 2(0.5,0)
F1812
  rect 1.78x3.3 smd: 1(-2.305,0) 2(2.305,0)
FPC-30P-0P5
  rect 0.3x1.3 smd: 1(-7.25,1.35) 2(-6.75,1.35) 3(-6.25,1.35) 4(-5.75,1.35) 5(-5.25,1.35) 6(-4.75,1.35) 7(-4.25,1.35) 8(-3.75,1.35) 9(-3.25,1.35) 10(-2.75,1.35) 11(-2.25,1.35) 12(-1.75,1.35) 13(-1.25,1.35) 14(-0.75,1.35) 15(-0.25,1.35) 16(0.25,1.35) 17(0.75,1.35) 18(1.25,1.35) 19(1.75,1.35) 20(2.25,1.35) 21(2.75,1.35) 22(3.25,1.35) 23(3.75,1.35) 24(4.25,1.35) 25(4.75,1.35) 26(5.25,1.35) 27(5.75,1.35) 28(6.25,1.35) 29(6.75,1.35) 30(7.25,1.35)
  rect 1.6x2 smd: 31(9.4,-1.35) 32(-9.4,-1.35)
FPC_24P_0P5
  rect 0.3x1.3 smd: 1(-5.75,-1.351) 2(-5.25,-1.351) 3(-4.75,-1.351) 4(-4.25,-1.351) 5(-3.75,-1.351) 6(-3.25,-1.351) 7(-2.75,-1.351) 8(-2.25,-1.351) 9(-1.75,-1.351) 10(-1.25,-1.351) 11(-0.75,-1.351) 12(-0.25,-1.351) 13(0.25,-1.351) 14(0.75,-1.351) 15(1.25,-1.351) 16(1.75,-1.351) 17(2.25,-1.351) 18(2.75,-1.351) 19(3.25,-1.351) 20(3.75,-1.351) 21(4.25,-1.351) 22(4.75,-1.351) 23(5.25,-1.351) 24(5.75,-1.351)
  rect 1.6x2 smd: 25(7.45,1.351) 26(-7.45,1.351)
GH1P25_TH_2P
  rect 0.9x0.9 hole 0.5: 1(-0.625,0)
  round 0.9 hole 0.5: 2(0.625,0)
HDMI-SMD
  round 2 hole 2 unplated: (-6.05,-2) (7.2,1.5)
  round 0.8 hole 0.55: 1(5.3,0.5) 2(4.731,-0.5) 3(4.145,0.5) 4(3.575,-0.5) 5(2.99,0.5) 6(2.419,-0.5) 7(1.835,0.5) 8(1.263,-0.5) 9(0.68,0.5) 10(0.107,-0.5) 11(-0.475,0.5) 12(-1.049,-0.5) 13(-1.63,0.5) 14(-2.205,-0.5) 15(-2.785,0.5) 16(-3.361,-0.5) 17(-3.94,0.5) 18(-4.517,-0.5) 19(-5.095,0.5)
  oval 3.2x1.4 hole 2.7x0.9: G1(-6.05,3.25) G2(3.45,3.25) G3(-2.95,-3.25) G4(6.05,-3.25)
HY911130A
  round 3.25 hole 3.25 unplated: (-5.715,0) (5.715,0)
  round 1.6 hole 1: 1(5.72,-8.89) 2(4.45,-6.35) 3(3.18,-8.89) 4(1.91,-6.35) 5(0.64,-8.89) 6(-0.63,-6.35) 7(-1.9,-8.89) 8(-3.17,-6.35) 9(-4.44,-8.89) 10(-5.71,-6.35)
  round 1.8 hole 1.2: 11(6.625,4.9) 12(4.085,4.9) 13(-4.085,4.9) 14(-6.625,4.9)
  round 2.43 hole 1.83: 15(7.745,-3.05) 16(-7.745,-3.05)
L0603
  rect 0.8x0.8 smd: 1(-0.8,0) 2(0.8,0)
L2520
  rect 1.118x2.032 smd: 1(-0.959,0) 2(0.959,0)
L4520
  rect 1.4x2.3 smd: 1(-1.8,0) 2(1.8,0)
LED_HS_0602_UR
  rect 0.77x0.6 smd: 1(0.815,0) 2(-0.815,0)
M2_NGFF_M_KEY
  round 1.1 hole 1.1 unplated: (-10,-1.475)
  round 1.6 hole 1.6 unplated: (10,-1.475)
  rect 0.3x1.55 smd: 1(-9.25,3.725) 2(-9,-3.725) 3(-8.75,3.725) 4(-8.5,-3.725) 5(-8.25,3.725) 6(-8,-3.725) 7(-7.75,3.725) 8(-7.5,-3.725) 9(-7.25,3.725) 10(-7,-3.725) 11(-6.75,3.725) 12(-6.5,-3.725) 13(-6.25,3.725) 14(-6,-3.725) 15(-5.75,3.725) 16(-5.5,-3.725) 17(-5.25,3.725) 18(-5,-3.725) 19(-4.75,3.725) 20(-4.5,-3.725) 21(-4.25,3.725) 22(-4,-3.725) 23(-3.75,3.725) 24(-3.5,-3.725) 25(-3.25,3.725) 26(-3,-3.725) 27(-2.75,3.725) 28(-2.5,-3.725) 29(-2.25,3.725) 30(-2,-3.725) 31(-1.75,3.725) 32(-1.5,-3.725) 33(-1.25,3.725) 34(-1,-3.725) 35(-0.75,3.725) 36(-0.5,-3.725) 37(-0.25,3.725) 38(0,-3.725) 39(0.25,3.725) 40(0.5,-3.725) 41(0.75,3.725) 42(1,-3.725) 43(1.25,3.725) 44(1.5,-3.725) 45(1.75,3.725) 46(2,-3.725) 47(2.25,3.725) 48(2.5,-3.725) 49(2.75,3.725) 50(3,-3.725) 51(3.25,3.725) 52(3.5,-3.725) 53(3.75,3.725) 54(4,-3.725) 55(4.25,3.725) 56(4.5,-3.725) 57(4.75,3.725) 58(5,-3.725) 67(7.25,3.725) 68(7.5,-3.725) 69(7.75,3.725) 70(8,-3.725) 71(8.25,3.725) 72(8.5,-3.725) 73(8.75,3.725) 74(9,-3.725) 75(9.25,3.725)
  rect 1.2x2.75 smd: 76(10.35,3.025) 77(-10.35,3.025)
NANO_SIM
  round 0.9 hole 0.9 unplated: (-5,-5.49) (3.5,-5.49)
  rect 0.5x1.3 smd: 1(0.25,6.74) 2(-2.29,6.74) 3(-4.83,6.74) 4(2.47,6.74) 5(1.52,6.74) 6(-1.02,6.74) 7(-3.56,6.74)
  rect 1x2.1 smd: 8(-6.5,5.26) 9(6.5,5.26) 10(-6.5,-6.74) 11(6.5,-6.74)
NPTH_M3
  round 3.2 hole 3.2 unplated: (0,0)
PCIE_52P
  round 1.6 hole 1.6 unplated: (-12.5,0)
  round 1.1 hole 1.1 unplated: (12.5,0)
  rect 0.6x2 smd: 1(-11.8,-4.1) 2(-11.4,4.1) 3(-11,-4.1) 4(-10.6,4.1) 5(-10.2,-4.1) 6(-9.8,4.1) 7(-9.4,-4.1) 8(-9,4.1) 9(-8.6,-4.1) 10(-8.2,4.1) 11(-7.8,-4.1) 12(-7.4,4.1) 13(-7,-4.1) 14(-6.6,4.1) 15(-6.2,-4.1) 16(-5.8,4.1) 17(-2.2,-4.1) 18(-1.8,4.1) 19(-1.4,-4.1) 20(-1,4.1) 21(-0.6,-4.1) 22(-0.2,4.1) 23(0.2,-4.1) 24(0.6,4.1) 25(1,-4.1) 26(1.4,4.1) 27(1.8,-4.1) 28(2.2,4.1) 29(2.6,-4.1) 30(3,4.1) 31(3.4,-4.1) 32(3.8,4.1) 33(4.2,-4.1) 34(4.6,4.1) 35(5,-4.1) 36(5.4,4.1) 37(5.8,-4.1) 38(6.2,4.1) 39(6.6,-4.1) 40(7,4.1) 41(7.4,-4.1) 42(7.8,4.1) 43(8.2,-4.1) 44(8.6,4.1) 45(9,-4.1) 46(9.4,4.1) 47(9.8,-4.1) 48(10.2,4.1) 49(10.6,-4.1) 50(11,4.1) 51(11.4,-4.1) 52(11.8,4.1)
  rect 2.15x2.6 smd: 53(14.65,-3.5) 54(-14.65,-3.5)
PH-1X2-2P0_L
  rect 1.1x1.1 hole 0.7: 1(-1,0)
  round 1.1 hole 0.7: 2(1,0)
PH-1X4-2P0
  rect 1.1x1.1 hole 0.7: 1(-3,0)
  round 1.1 hole 0.7: 2(-1,0) 3(1,0) 4(3,0)
PH-1X6-2P0
  rect 1.1x1.1 hole 0.7: 1(-5,0)
  round 1.1 hole 0.7: 2(-3,0) 3(-1,0) 4(1,0) 5(3,0) 6(5,0)
QFN24
  rect 1x0.3 smd: 1(-2.1,1.25) 2(-2.1,0.75) 3(-2.1,0.25) 4(-2.1,-0.25) 5(-2.1,-0.75) 6(-2.1,-1.25) 13(2.1,-1.25) 14(2.1,-0.75) 15(2.1,-0.25) 16(2.1,0.25) 17(2.1,0.75) 18(2.1,1.25)
  rect 0.3x1 smd: 7(-1.25,-2.1) 8(-0.75,-2.1) 9(-0.25,-2.1) 10(0.25,-2.1) 11(0.75,-2.1) 12(1.25,-2.1) 19(1.25,2.1) 20(0.75,2.1) 21(0.25,2.1) 22(-0.25,2.1) 23(-0.75,2.1) 24(-1.25,2.1)
  rect 2x2 smd: 25(0,0)
QFP_40P_R
  oval 0.8x0.22 smd: 1(-2.5,1.8) 2(-2.5,1.4) 3(-2.5,1) 4(-2.5,0.6) 5(-2.5,0.2) 6(-2.5,-0.2) 7(-2.5,-0.6) 8(-2.5,-1) 9(-2.5,-1.4) 10(-2.5,-1.8) 21(2.5,-1.8) 22(2.5,-1.4) 23(2.5,-1) 24(2.5,-0.6) 25(2.5,-0.2) 26(2.5,0.2) 27(2.5,0.6) 28(2.5,1) 29(2.5,1.4) 30(2.5,1.8)
  oval 0.22x0.8 smd: 11(-1.8,-2.5) 12(-1.4,-2.5) 13(-1,-2.5) 14(-0.6,-2.5) 15(-0.2,-2.5) 16(0.2,-2.5) 17(0.6,-2.5) 18(1,-2.5) 19(1.4,-2.5) 20(1.8,-2.5) 31(1.8,2.5) 32(1.4,2.5) 33(1,2.5) 34(0.6,2.5) 35(0.2,2.5) 36(-0.2,2.5) 37(-0.6,2.5) 38(-1,2.5) 39(-1.4,2.5) 40(-1.8,2.5)
  rect 3x3 smd: 41(0,0)
R0402
  rect 0.599x0.599 smd: 1(-0.5,0) 2(0.5,0)
R0603
  rect 0.8x0.8 smd: 1(-0.8,0) 2(0.8,0)
R0805
  rect 1.016x1.143 smd: 1(-1.016,0) 2(1.016,0)
SGDBF-05-80P-H30
  round 0.6 hole 0.6 unplated: (-10.7,-1.25) (10.7,-1.25)
  rect 0.25x2 smd: 1(9.75,-2) 2(9.75,2) 3(9.25,-2) 4(9.25,2) 5(8.75,-2) 6(8.75,2) 7(8.25,-2) 8(8.25,2) 9(7.75,-2) 10(7.75,2) 11(7.25,-2) 12(7.25,2) 13(6.75,-2) 14(6.75,2) 15(6.25,-2) 16(6.25,2) 17(5.75,-2) 18(5.75,2) 19(5.25,-2) 20(5.25,2) 21(4.75,-2) 22(4.75,2) 23(4.25,-2) 24(4.25,2) 25(3.75,-2) 26(3.75,2) 27(3.25,-2) 28(3.25,2) 29(2.75,-2) 30(2.75,2) 31(2.25,-2) 32(2.25,2) 33(1.75,-2) 34(1.75,2) 35(1.25,-2) 36(1.25,2) 37(0.75,-2) 38(0.75,2) 39(0.25,-2) 40(0.25,2) 41(-0.25,-2) 42(-0.25,2) 43(-0.75,-2) 44(-0.75,2) 45(-1.25,-2) 46(-1.25,2) 47(-1.75,-2) 48(-1.75,2) 49(-2.25,-2) 50(-2.25,2) 51(-2.75,-2) 52(-2.75,2) 53(-3.25,-2) 54(-3.25,2) 55(-3.75,-2) 56(-3.75,2) 57(-4.25,-2) 58(-4.25,2) 59(-4.75,-2) 60(-4.75,2) 61(-5.25,-2) 62(-5.25,2) 63(-5.75,-2) 64(-5.75,2) 65(-6.25,-2) 66(-6.25,2) 67(-6.75,-2) 68(-6.75,2) 69(-7.25,-2) 70(-7.25,2) 71(-7.75,-2) 72(-7.75,2) 73(-8.25,-2) 74(-8.25,2) 75(-8.75,-2) 76(-8.75,2) 77(-9.25,-2) 78(-9.25,2) 79(-9.75,-2) 80(-9.75,2)
SGDBM-05-80P-H10
  round 0.6 hole 0.6 unplated: (-10.7,-1.25) (10.7,-1.25)
  rect 0.25x2 smd: 1(-9.75,-2) 2(-9.75,2) 3(-9.25,-2) 4(-9.25,2) 5(-8.75,-2) 6(-8.75,2) 7(-8.25,-2) 8(-8.25,2) 9(-7.75,-2) 10(-7.75,2) 11(-7.25,-2) 12(-7.25,2) 13(-6.75,-2) 14(-6.75,2) 15(-6.25,-2) 16(-6.25,2) 17(-5.75,-2) 18(-5.75,2) 19(-5.25,-2) 20(-5.25,2) 21(-4.75,-2) 22(-4.75,2) 23(-4.25,-2) 24(-4.25,2) 25(-3.75,-2) 26(-3.75,2) 27(-3.25,-2) 28(-3.25,2) 29(-2.75,-2) 30(-2.75,2) 31(-2.25,-2) 32(-2.25,2) 33(-1.75,-2) 34(-1.75,2) 35(-1.25,-2) 36(-1.25,2) 37(-0.75,-2) 38(-0.75,2) 39(-0.25,-2) 40(-0.25,2) 41(0.25,-2) 42(0.25,2) 43(0.75,-2) 44(0.75,2) 45(1.25,-2) 46(1.25,2) 47(1.75,-2) 48(1.75,2) 49(2.25,-2) 50(2.25,2) 51(2.75,-2) 52(2.75,2) 53(3.25,-2) 54(3.25,2) 55(3.75,-2) 56(3.75,2) 57(4.25,-2) 58(4.25,2) 59(4.75,-2) 60(4.75,2) 61(5.25,-2) 62(5.25,2) 63(5.75,-2) 64(5.75,2) 65(6.25,-2) 66(6.25,2) 67(6.75,-2) 68(6.75,2) 69(7.25,-2) 70(7.25,2) 71(7.75,-2) 72(7.75,2) 73(8.25,-2) 74(8.25,2) 75(8.75,-2) 76(8.75,2) 77(9.25,-2) 78(9.25,2) 79(9.75,-2) 80(9.75,2)
SMD4-6R80X2R50
  rect 0.8x1.2 smd: 1(1.905,0) 2(0.635,0) 3(-0.635,0) 4(-1.905,0)
SMTSO-M2R5
  round 6.2 hole 4.22: 1(0,0)
SMTSO-M3
  round 6.2 hole 4.22: 1(0,0)
SOD323
  rect 1x0.83 smd: 1(1.18,0) 2(-1.18,0)
SOD323_T
  rect 0.8x0.8 smd: 1(-1.175,0) 2(1.175,0)
SOD523
  rect 0.6x0.7 smd: 1(-0.71,0) 2(0.71,0)
SOD-123
  rect 1.2x1.4 smd: 1(1.7,0) 2(-1.7,0)
SOIC8-208
  rect 1.778x0.635 smd: 1(-4,1.905) 2(-4,0.635) 3(-4,-0.635) 4(-4,-1.905) 5(4,-1.905) 6(4,-0.635) 7(4,0.635) 8(4,1.905)
SOIC16
  oval 2.032x0.61 smd: 1(-2.789,4.44) 2(-2.789,3.18) 3(-2.789,1.9) 4(-2.789,0.64) 5(-2.789,-0.64) 6(-2.789,-1.9) 7(-2.789,-3.18) 8(-2.789,-4.44) 9(2.789,-4.44) 10(2.789,-3.18) 11(2.789,-1.9) 12(2.789,-0.64) 13(2.789,0.64) 14(2.789,1.9) 15(2.789,3.18) 16(2.789,4.44)
SOP8
  oval 1.651x0.635 smd: 1(-2.6,1.905) 2(-2.6,0.635) 3(-2.6,-0.635) 4(-2.6,-1.905) 5(2.6,-1.905) 6(2.6,-0.635) 7(2.6,0.635) 8(2.6,1.905)
SOP-8
  oval 0.7x1.7 smd: 1(-1.905,-3.1) 2(-0.635,-3.1) 3(0.635,-3.1) 4(1.905,-3.1) 5(1.905,3.1) 6(0.635,3.1) 7(-0.635,3.1) 8(-1.905,3.1)
SOT23
  rect 0.914x0.914 smd: 1(-0.953,-0.991) 2(0.953,-0.991)
  rect 0.914x1.27 smd: 3(0,1.041)
SOT23-5
  rect 0.599x1.199 smd: 1(-0.95,-1.25) 2(0,-1.25) 3(0.95,-1.25) 4(0.95,1.25) 5(-0.95,1.25)
SOT23_6
  rect 0.7x0.9 smd: 1(-0.95,-1.2) 2(0,-1.2) 3(0.95,-1.2) 4(0.95,1.2) 5(0,1.2) 6(-0.95,1.2)
SOT563
  rect 0.3x0.45 smd: 1(-0.5,-0.675) 2(0,-0.675) 3(0.5,-0.675) 4(0.5,0.675) 5(0,0.675) 6(-0.5,0.675)
SOT-353
  rect 0.406x1.194 smd: 1(-0.65,-0.9) 2(0,-0.9) 3(0.65,-0.9) 4(0.65,0.9) 5(-0.65,0.9)
SSATA_V
  round 1.1 hole 0.75: 1(-3.81,0) 2(-2.54,-1) 3(-1.27,-1) 4(0,0) 5(1.27,-1) 6(2.54,-1) 7(3.81,0)
  round 2.1 hole 1.5: S1(6.48,-0.5) S2(-6.48,-0.5)
SW_TH_3P_4R5X5R5
  round 1.4 hole 0.8: 1(-1.55,0.975) 2(1.55,0.975) 3(0,-0.975)
T3R2-5R2_TOPSMT
  round 5.2 hole 3.2: 1(0,0)
TFCARD
  round 1.016 hole 1.016 unplated: (-4,0) (4,0)
  rect 0.7x1.6 smd: 1(3.2,10.5) 2(2.1,10.5) 3(1,10.5) 4(-0.1,10.5) 5(-1.2,10.5) 6(-2.3,10.5) 7(-3.4,10.5) 8(-4.5,10.5) 9(-5.6,10.5)
  rect 1.2x1.778 smd: 10(-6.8,10)
  rect 1.524x2.413 smd: 11(-6.8,0.4) 12(8.7,0.4)
  rect 1.778x1.778 smd: 13(7.8,10)
TP_1MM
  round 1.016 smd: 1(0,0)
TSSOP20
  rect 0.4x1.5 smd: 1(-2.925,-3) 2(-2.275,-3) 3(-1.625,-3) 4(-0.975,-3) 5(-0.325,-3) 6(0.325,-3) 7(0.975,-3) 8(1.625,-3) 9(2.275,-3) 10(2.925,-3) 11(2.925,3) 12(2.275,3) 13(1.625,3) 14(0.975,3) 15(0.325,3) 16(-0.325,3) 17(-0.975,3) 18(-1.625,3) 19(-2.275,3) 20(-2.925,3)
TYPE-C-31-M-12
  round 0.65 hole 0.65 unplated: (-2.89,-1.44) (2.89,-1.44)
  rect 0.3x2 smd: A1(-3.35,0.279) A4(-2.55,0.279) A5(-1.25,0.279) A6(-0.249,0.279) A7(0.249,0.279) A8(1.25,0.279) A9(2.55,0.279) A12(3.35,0.279) B1(3.05,0.279) B4(2.25,0.279) B5(1.75,0.279) B6(0.749,0.279) B7(-0.749,0.279) B8(-1.75,0.279) B9(-2.25,0.279) B12(-3.05,0.279)
  oval 1.1x1.7 hole 0.6x1.2: C1(-4.32,-5.1) C2(4.32,-5.1)
  oval 1.1x2.2 hole 0.6x1.7: C3(-4.32,-0.909) C4(4.32,-0.909)
unnamed
  round 1.016 smd: 1(0,0)
USB3D0-AF-18P
  round 1.1 hole 0.7: 1(-3.5,-1.5) 2(-1,-1.5) 3(1,-1.5) 4(3.5,-1.5) 5(4,0) 6(2,0) 7(0,0) 8(-2,0) 9(-4,0) 10(-3.5,1.7) 11(-1,1.7) 12(1,1.7) 13(3.5,1.7) 14(4,3.2) 15(2,3.2) 16(0,3.2) 17(-2,3.2) 18(-4,3.2)
  round 3.2 hole 2.4: 19(6.57,-3.5) 20(6.57,2.18) 21(-6.57,2.18) 22(-6.57,-3.5)
USB-A-D
  round 1.651 hole 1: 1(3.5,-6.5) 2(1,-6.5) 3(-1,-6.5) 4(-3.5,-6.5) 7(3.5,-3.5) 8(1,-3.5) 9(-1,-3.5) 10(-3.5,-3.5)
  round 3.3 hole 2: 5(-6.55,-6.5) 6(6.55,-6.5) 11(-6.55,-0.7) 12(6.55,-0.7)
USON_10
  rect 0.3x0.55 smd: 1(-1,-0.4) 2(-0.5,-0.4) 4(0.5,-0.4) 5(1,-0.4) 6(1,0.4) 7(0.5,0.4) 9(-0.5,0.4) 10(-1,0.4)
  rect 0.4x0.55 smd: 3(0,-0.4) 8(0,0.4)
XH2P54-4P
  rect 1.45x1.45 hole 0.85: 1(-3.81,0)
  round 1.45 hole 0.85: 2(-1.27,0) 3(1.27,0) 4(3.81,0)
ZH1P5MM_TH_2P
  round 1.05 hole 0.65: 1(-0.75,0) 2(0.75,0)

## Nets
1V05_AVDD_PHY0: C84.1 C85.1 C86.1 C87.1 R114.2 U18.3(AVDD10_2) U18.8(AVDD10_1) U18.38(AVDD10)
1V05_AVDD_PHY1: C105.1 C106.1 C107.1 C108.1 R141.2 U19.3(AVDD10_2) U19.8(AVDD10_1) U19.38(AVDD10)
1V05_DVDD_PHY0: C82.1 C83.1 R113.1 U18.21(DVDD10)
1V05_DVDD_PHY1: C103.1 C104.1 R140.1 U19.21(DVDD10)
1V05_PHY0: C74.1 C75.1 L9.2 R113.2 R114.1
1V05_PHY1: C96.1 C97.1 L13.2 R140.2 R141.1
1V8_DVDD_PHY0: C72.1 C73.1 C81.1 L10.1 R88.1 R89.1 R90.1 R101.1 R102.1 R107.1 U18.28(DVDD_RG)
1V8_DVDD_PHY1: C94.1 C95.1 C102.1 L14.1 R115.1 R116.1 R117.1 R128.1 R129.1 R136.1 U19.28(DVDD_RG)
3V3_AVDD_PHY0: C91.1 C92.1 C93.1 L12.1 U18.11(AVDD33_1) U18.40(AVDD33)
3V3_AVDD_PHY1: C112.1 C113.1 C114.1 L16.1 U19.11(AVDD33_1) U19.40(AVDD33)
3V3_DVDD_PHY0: C88.1 C89.1 C90.1 L11.1 R28.2 R103.1 R109.2 R110.2 R184.1 U18.29(DVDD33)
3V3_DVDD_PHY1: C109.1 C110.1 C111.1 L15.1 R130.1 R133.2 R138.2 R139.2 R238.1 U19.29(DVDD33)
12V: C5.1 C6.1 C7.1 C8.1 C9.1 C10.1 C18.1 C19.1 C27.1 C160.1 C179.1 C180.1 C181.1 C182.1 C209.1 C210.1 C218.1 F1.2 J29.26 J29.27 J29.28 J29.29 J37.1 Q10.2(SOURCE) R205.1 R225.2 U1.3(VIN) U2.3(VIN) U5.3(VIN) U16.3(VIN) U41.3(VIN)
12V_IN: F1.1 J39.4
